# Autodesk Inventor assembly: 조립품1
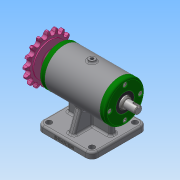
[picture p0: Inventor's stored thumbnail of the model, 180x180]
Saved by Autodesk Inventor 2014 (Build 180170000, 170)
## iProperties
Created: 2019-06
Part Number: 조립품1
Document SubType Name: Assembly
Designer: net
Author: net
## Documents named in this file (9)
- C:\Users\net\Desktop\조립품1.iam
- C:\Users\net\Desktop\부품1.ipt
- C:\Users\net\Desktop\490604V1028\커버.ipt
- C:\Users\net\Desktop\490604V1028\베어링 6203.ipt
- C:\Users\net\Desktop\490604V1028\볼트 M4.ipt
- C:\Users\net\Desktop\490604V1028\축.ipt
- C:\Users\net\Desktop\490604V1028\키 4x4x12.ipt
- C:\Users\net\Desktop\490604V1028\오일 실 17 30 5.ipt
- C:\Users\net\Desktop\490604V1028\스프로킷.ipt
